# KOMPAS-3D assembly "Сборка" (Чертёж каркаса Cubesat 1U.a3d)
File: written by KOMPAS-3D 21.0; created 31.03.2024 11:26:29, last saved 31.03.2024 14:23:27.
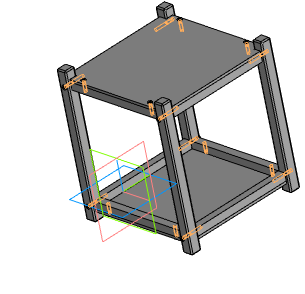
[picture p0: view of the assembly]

Document properties: Автор: Школа; Полное имя файла: C:\Users\Школа\Desktop\КУБСАТ ПРЕДПРОФФ\Спутник.a3d

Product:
- Part/product: Сборка
    Масса: 0.720509
  - Component [detail]: Деталь  | pos. 7  | Масса: 0.139417; source file: Крышка.m3d
  - Component [detail]: Деталь  | pos. 14  | Масса: 0.139417; source file: Крышка.m3d
  - Component [detail]: Деталь  | pos. 8  | Масса: 0.025406; source file: Ребро.m3d
  - Component [detail]: Деталь  | pos. 5  | Масса: 0.02427; source file: Ребро2.m3d
  - Component [detail]: Деталь  | pos. 2  | Масса: 0.02427; source file: Ребро2.m3d
  - Component [detail]: Деталь  | pos. 9  | Масса: 0.05997; source file: Контур.m3d
  - Component [detail]: Деталь  | pos. 3  | Масса: 0.05997; source file: Контур.m3d
  - Component [detail]: Деталь  | pos. 4  | Масса: 0.025406; source file: Ребро.m3d
  - Component [detail]: Деталь  | pos. 10  | Масса: 0.05997; source file: Контур.m3d
  - Component [detail]: Деталь  | pos. 15  | Масса: 0.025406; source file: Ребро.m3d
  - Component [detail]: Деталь  | pos. 12  | Масса: 0.02427; source file: Ребро2.m3d
  - Component [detail]: Деталь  | pos. 11  | Масса: 0.02427; source file: Ребро2.m3d
  - Component [detail]: Деталь  | pos. 6  | Масса: 0.05997; source file: Контур.m3d
  - Component [detail]: Деталь  | pos. 13  | Масса: 0.025406; source file: Ребро.m3d
  - Component [standard]: Винт с потайной головкой ГОСТ Р ИСО 7046-1 - М2 x 8-H  | qty 8  | pos. 1  | Материал: Не определено (density 1000 kg/m3); Масса: 0.000193; Раздел спецификации: Стандартные изделия; Рассекать на разрезах: no; additional columns: ГОСТ Р ИСО 7046-1-2013; М2 x 8 - H
  - Component [standard]: Винт с потайной головкой ГОСТ Р ИСО 7046-1 - М2 x 8-H  | qty 8  | pos. 16  | Материал: Не определено (density 1000 kg/m3); Масса: 0.000193; Раздел спецификации: Стандартные изделия; Рассекать на разрезах: no; additional columns: ГОСТ Р ИСО 7046-1-2013; М2 x 8 - H

Referenced files in C:\Users\Школа\Desktop\КУБСАТ ПРЕДПРОФФ\: Ребро2.m3d, Контур.m3d, Ребро.m3d, Крышка.m3d
Referenced files in D:\Libs\PARTLib\DATA\vault\Methods\Kompas\3D\: PLib_Screw_ISO_7046_1500.m3d
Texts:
  Винт с потайной головкой
  ГОСТ Р ИСО
  Деталь (1)
  Деталь (2)
  Деталь (3)
  Деталь (4)
  Винт с потайной головкой ГОСТ Р ИСО 7046-1 - М2 x 8-H (1)
  Винт с потайной головкой ГОСТ Р ИСО 7046-1 - М2 x 8-H (2)
  Винт с потайной головкой ГОСТ Р ИСО 7046-1 - М2 x 8-H (3)
  Винт с потайной головкой ГОСТ Р ИСО 7046-1 - М2 x 8-H (4)
  Винт с потайной головкой ГОСТ Р ИСО 7046-1 - М2 x 8-H (5)
  Винт с потайной головкой ГОСТ Р ИСО 7046-1 - М2 x 8-H (6)
  Conus Countersunk flat head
